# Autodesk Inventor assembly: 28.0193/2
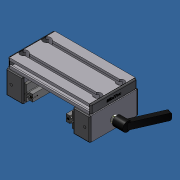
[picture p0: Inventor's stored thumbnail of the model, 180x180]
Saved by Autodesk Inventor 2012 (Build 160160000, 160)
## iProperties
Created: 2007-06
Part Number: 28.0193/2
Document SubType Name: Assembly
Designer: Andy Moles
Description: SLIDE LWN 32X45-90 WITH SIDE CLAMP
Mass: 884.75 g
Surface Area: 2200.73 cm^2
Volume: 340.475 cm^3
Density: 2.59858 g/cm^3
Author: Andy Moles
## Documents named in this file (12)
- C:\Andys Backup Data\ANDY'S INVENTOR\INVENTOR LIBRARIES\PARTS LIBRARY\READY FOR USE MODULES LG\28.0193_2 SLIDE LWN 32X45-90 WITH SIDE CLAMP.iam
- C:\Andys Backup Data\ANDY'S INVENTOR\INVENTOR LIBRARIES\PARTS LIBRARY\READY FOR USE MODULES LG\SUBCOMPONENTS\28.0126 SLIDE 45X32.ipt
- C:\Andys Backup Data\ANDY'S INVENTOR\INVENTOR LIBRARIES\PARTS LIBRARY\COMPONENTS LG\22.1095 SLIDE RAIL LN.iam
- C:\Andys Backup Data\ANDY'S INVENTOR\INVENTOR LIBRARIES\PARTS LIBRARY\FASTENING ELEMENTS\SCREWS CAP\21.1200 M8X16.ipt
- C:\Andys Backup Data\ANDY'S INVENTOR\INVENTOR LIBRARIES\PARTS LIBRARY\FASTENING ELEMENTS\NUTS\21.1351 M8 SQUARE NUT.ipt
- C:\Andys Backup Data\ANDY'S INVENTOR\INVENTOR LIBRARIES\PARTS LIBRARY\COMPONENTS LG\22.1095_9 SLIDE RAIL LN FOR SIDE LOCK.iam
- C:\Andys Backup Data\ANDY'S INVENTOR\INVENTOR LIBRARIES\PARTS LIBRARY\READY FOR USE MODULES LG\SUBCOMPONENTS\28.0126_9 SIDE LOCK 45X32.ipt
- C:\Andys Backup Data\ANDY'S INVENTOR\INVENTOR LIBRARIES\PARTS LIBRARY\COMPONENTS LG\21.1014_2 SLIDE LOCK WITH M6X51 STUD.ipt
- C:\Andys Backup Data\ANDY'S INVENTOR\INVENTOR LIBRARIES\PARTS LIBRARY\FASTENING ELEMENTS\NUTS\21.1330 M6 SQUARE NUT.ipt
- C:\Andys Backup Data\ANDY'S INVENTOR\INVENTOR LIBRARIES\PARTS LIBRARY\READY FOR USE MODULES LG\SUBCOMPONENTS\28.0224 SLIDE LWN 32X45-90 90X19.ipt
- C:\Andys Backup Data\ANDY'S INVENTOR\INVENTOR LIBRARIES\PARTS LIBRARY\END CAPS\22.1014_1 END CAP 90X19 GRAY.ipt
- C:\Andys Backup Data\ANDY'S INVENTOR\INVENTOR LIBRARIES\PARTS LIBRARY\END CAPS\22.1003_1 END CAP 45x32 Z Gray.iam
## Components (21 placed, 11 different names)
1. 28.0224 SLIDE LWN 32X45-90 90X19:1 — Mate:1, Mate:2, Flush:1, Mate:4, Flush:4, Flush:5, Flush:18, Flush:19, Insert:1, Insert:2, Insert:3, Insert:4, Insert:5, Insert:6, Insert:7, Insert:8, Mate:15, Flush:20, Flush:21, Mate:22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
2. 28.0126 SLIDE 45X32:2 — Mate:4, Flush:4, Flush:5, Mate:13, Mate:14, Mate:25, Flush:32, Flush:33, Mate:26, Flush:34, Flush:35
3. 22.1014_1 END CAP 90X19 GRAY:1 — Mate:23, Flush:28, Flush:29
4. 22.1014_1 END CAP 90X19 GRAY:2 — Mate:22, Flush:26, Flush:27
5. 22.1095_9 SLIDE RAIL LN FOR SIDE LOCK:1 [sub-assembly] — Flush:18, Mate:17, Mate:19, Mate:20
6. 22.1095 SLIDE RAIL LN:3 [sub-assembly] — Mate:13, Flush:19, Mate:14
7. 21.1200 M8 x 16:1 — Insert:1
8. 21.1200 M8 x 16:2 — Insert:2
9. 21.1200 M8 x 16:3 — Insert:3
10. 21.1200 M8 x 16:4 — Insert:4
11. 21.1351 M8 SQUARE NUT:1 — Insert:5
12. 21.1351 M8 SQUARE NUT:2 — Insert:6
13. 21.1351 M8 SQUARE NUT:3 — Insert:8
14. 21.1351 M8 SQUARE NUT:4 — Insert:7
15. 28.0126_9 SIDE LOCK 45X32:1 — Mate:15, Flush:20, Flush:21, Insert:9, Mate:19, Mate:20, Mate:24, Flush:30, Flush:31, Mate:27, Flush:36, Flush:37
16. 21.1014_2 SLIDE LOCK WITH M6X51 STUD:1 — Insert:9, Mate:16
17. 21.1330 M6 SQUARE NUT:1 — Mate:16, Mate:17
18. 22.1003_1 END CAP 45x32 Z Gray:1 [sub-assembly] — Mate:26, Flush:34, Flush:35
19. 22.1003_1 END CAP 45x32 Z Gray:2 [sub-assembly] — Mate:25, Flush:32, Flush:33
20. 22.1003_1 END CAP 45x32 Z Gray:3 [sub-assembly] — Mate:27, Flush:36, Flush:37
21. 22.1003_1 END CAP 45x32 Z Gray:4 [sub-assembly] — Mate:24, Flush:30, Flush:31
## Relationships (44: Flush 19, Mate 16, Insert 9)
- Mate:1: 28.0224 SLIDE LWN 32X45-90 90X19:1
- Mate:2: 28.0224 SLIDE LWN 32X45-90 90X19:1
- Flush:1: 28.0224 SLIDE LWN 32X45-90 90X19:1
- Mate:4: 28.0224 SLIDE LWN 32X45-90 90X19:1 ↔ 28.0126 SLIDE 45X32:2
- Flush:4: 28.0224 SLIDE LWN 32X45-90 90X19:1 ↔ 28.0126 SLIDE 45X32:2
- Flush:5: 28.0224 SLIDE LWN 32X45-90 90X19:1 ↔ 28.0126 SLIDE 45X32:2
- Flush:18: 28.0224 SLIDE LWN 32X45-90 90X19:1 ↔ 22.1095_9 SLIDE RAIL LN FOR SIDE LOCK:1
- Mate:13: 28.0126 SLIDE 45X32:2 ↔ 22.1095 SLIDE RAIL LN:3
- Flush:19: 28.0224 SLIDE LWN 32X45-90 90X19:1 ↔ 22.1095 SLIDE RAIL LN:3
- Mate:14: 28.0126 SLIDE 45X32:2 ↔ 22.1095 SLIDE RAIL LN:3
- Insert:1: 28.0224 SLIDE LWN 32X45-90 90X19:1 ↔ 21.1200 M8 x 16:1
- Insert:2: 28.0224 SLIDE LWN 32X45-90 90X19:1 ↔ 21.1200 M8 x 16:2
- Insert:3: 28.0224 SLIDE LWN 32X45-90 90X19:1 ↔ 21.1200 M8 x 16:3
- Insert:4: 28.0224 SLIDE LWN 32X45-90 90X19:1 ↔ 21.1200 M8 x 16:4
- Insert:5: 28.0224 SLIDE LWN 32X45-90 90X19:1 ↔ 21.1351 M8 SQUARE NUT:1
- Insert:6: 28.0224 SLIDE LWN 32X45-90 90X19:1 ↔ 21.1351 M8 SQUARE NUT:2
- Insert:7: 28.0224 SLIDE LWN 32X45-90 90X19:1 ↔ 21.1351 M8 SQUARE NUT:4
- Insert:8: 28.0224 SLIDE LWN 32X45-90 90X19:1 ↔ 21.1351 M8 SQUARE NUT:3
- Mate:15: 28.0224 SLIDE LWN 32X45-90 90X19:1 ↔ 28.0126_9 SIDE LOCK 45X32:1
- Flush:20: 28.0224 SLIDE LWN 32X45-90 90X19:1 ↔ 28.0126_9 SIDE LOCK 45X32:1
- Flush:21: 28.0224 SLIDE LWN 32X45-90 90X19:1 ↔ 28.0126_9 SIDE LOCK 45X32:1
- Insert:9: 28.0126_9 SIDE LOCK 45X32:1 ↔ 21.1014_2 SLIDE LOCK WITH M6X51 STUD:1
- Mate:16: 21.1014_2 SLIDE LOCK WITH M6X51 STUD:1 ↔ 21.1330 M6 SQUARE NUT:1
- Mate:17: 22.1095_9 SLIDE RAIL LN FOR SIDE LOCK:1 ↔ 21.1330 M6 SQUARE NUT:1
- Mate:19: 22.1095_9 SLIDE RAIL LN FOR SIDE LOCK:1 ↔ 28.0126_9 SIDE LOCK 45X32:1
- Mate:20: 22.1095_9 SLIDE RAIL LN FOR SIDE LOCK:1 ↔ 28.0126_9 SIDE LOCK 45X32:1
- Mate:22: 28.0224 SLIDE LWN 32X45-90 90X19:1 ↔ 22.1014_1 END CAP 90X19 GRAY:2
- Flush:26: 28.0224 SLIDE LWN 32X45-90 90X19:1 ↔ 22.1014_1 END CAP 90X19 GRAY:2
- Flush:27: 28.0224 SLIDE LWN 32X45-90 90X19:1 ↔ 22.1014_1 END CAP 90X19 GRAY:2
- Mate:23: 28.0224 SLIDE LWN 32X45-90 90X19:1 ↔ 22.1014_1 END CAP 90X19 GRAY:1
- Flush:28: 28.0224 SLIDE LWN 32X45-90 90X19:1 ↔ 22.1014_1 END CAP 90X19 GRAY:1
- Flush:29: 28.0224 SLIDE LWN 32X45-90 90X19:1 ↔ 22.1014_1 END CAP 90X19 GRAY:1
- Mate:24: 28.0126_9 SIDE LOCK 45X32:1 ↔ 22.1003_1 END CAP 45x32 Z Gray:4
- Flush:30: 28.0126_9 SIDE LOCK 45X32:1 ↔ 22.1003_1 END CAP 45x32 Z Gray:4
- Flush:31: 28.0126_9 SIDE LOCK 45X32:1 ↔ 22.1003_1 END CAP 45x32 Z Gray:4
- Mate:25: 28.0126 SLIDE 45X32:2 ↔ 22.1003_1 END CAP 45x32 Z Gray:2
- Flush:32: 28.0126 SLIDE 45X32:2 ↔ 22.1003_1 END CAP 45x32 Z Gray:2
- Flush:33: 28.0126 SLIDE 45X32:2 ↔ 22.1003_1 END CAP 45x32 Z Gray:2
- Mate:26: 28.0126 SLIDE 45X32:2 ↔ 22.1003_1 END CAP 45x32 Z Gray:1
- Flush:34: 28.0126 SLIDE 45X32:2 ↔ 22.1003_1 END CAP 45x32 Z Gray:1
- Flush:35: 28.0126 SLIDE 45X32:2 ↔ 22.1003_1 END CAP 45x32 Z Gray:1
- Mate:27: 28.0126_9 SIDE LOCK 45X32:1 ↔ 22.1003_1 END CAP 45x32 Z Gray:3
- Flush:36: 28.0126_9 SIDE LOCK 45X32:1 ↔ 22.1003_1 END CAP 45x32 Z Gray:3
- Flush:37: 28.0126_9 SIDE LOCK 45X32:1 ↔ 22.1003_1 END CAP 45x32 Z Gray:3
